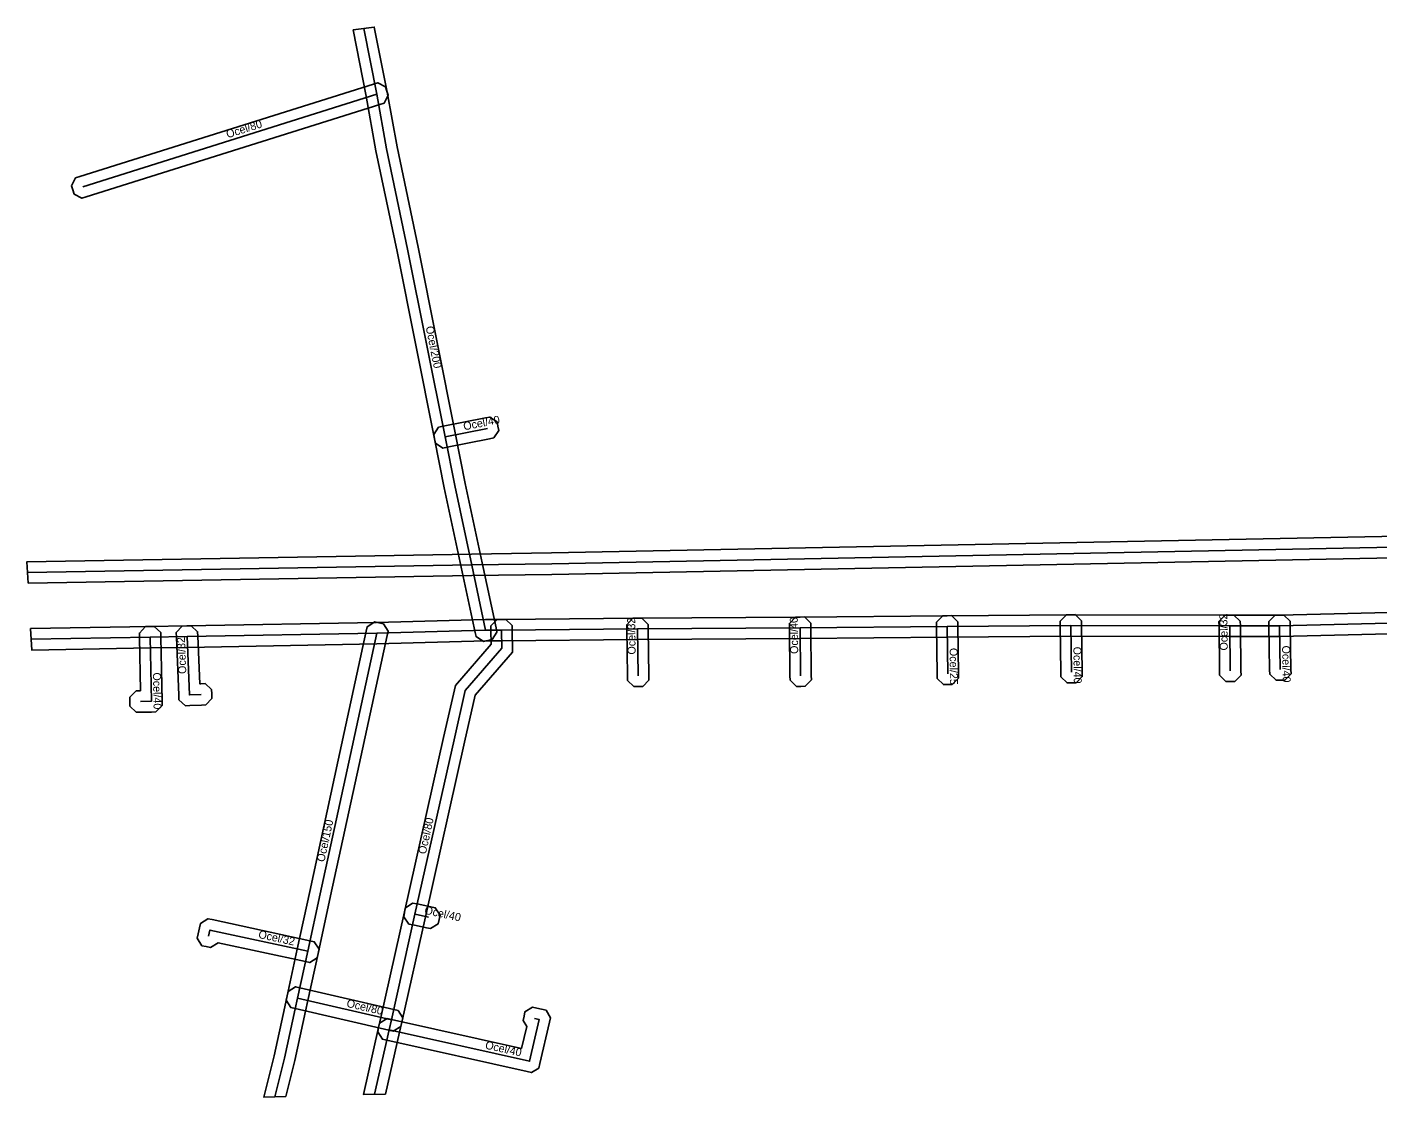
# Model space of a CAD drawing. Extents: x -702844 to -702342, y -1011731 to -1011542.
# Drawn here: x -702844.1 to -702717.5, y -1011730.8 to -1011630.5 of the extents above; entities that cross this region are included whole.
import ezdxf

# ---------------------------------------------------------------- set-up
doc = ezdxf.new("R2010")
doc.units = 0
for name, color, linetype in [('1', 7, 'Continuous'), ('14', 7, 'Continuous'), ('18', 7, 'Continuous'), ('20', 7, 'Continuous'), ('24', 7, 'Continuous')]:
    doc.layers.add(name, color=color, linetype=linetype)

msp = doc.modelspace()

# ---------------------------------------------------------------- linework, layer by layer
at = {"layer": '1'}
for points in [[(-702813.55, -1011630.76), (-702811.56, -1011630.49), (-702810.35, -1011636.6), (-702809.43, -1011641.71), (-702807.46, -1011651.12), (-702803.95, -1011668.69), (-702803.04, -1011673.26), (-702801.45, -1011680.7), (-702800.15, -1011686.8), (-702800.07, -1011687.21), (-702800.52, -1011687.9), (-702800.92, -1011687.99), (-702801.33, -1011688.08), (-702802.02, -1011687.62), (-702802.11, -1011687.22), (-702803.41, -1011681.12), (-702805, -1011673.67), (-702805.91, -1011669.08), (-702809.42, -1011651.52), (-702811.4, -1011642.09), (-702812.32, -1011636.97)], [(-702839.56, -1011644.62), (-702839.16, -1011644.5), (-702811.63, -1011635.84), (-702811.24, -1011635.71), (-702810.5, -1011636.09), (-702810.38, -1011636.49), (-702810.25, -1011636.88), (-702810.64, -1011637.62), (-702811.03, -1011637.74), (-702838.56, -1011646.41), (-702838.96, -1011646.53), (-702839.69, -1011646.15), (-702839.82, -1011645.76), (-702839.94, -1011645.36)], [(-702800.35, -1011669), (-702800.76, -1011669.08), (-702804.74, -1011669.87), (-702805.14, -1011669.95), (-702805.83, -1011669.48), (-702805.91, -1011669.08), (-702805.99, -1011668.67), (-702805.53, -1011667.98), (-702805.12, -1011667.9), (-702801.15, -1011667.12), (-702800.74, -1011667.04), (-702800.05, -1011667.5), (-702799.97, -1011667.91), (-702799.89, -1011668.31)], [(-702802.41, -1011681.9), (-702843.99, -1011682.6), (-702844.1, -1011680.6), (-702802.44, -1011679.9), (-702794.94, -1011679.78), (-702550.47, -1011674.95), (-702550.05, -1011674.94), (-702549.46, -1011675.51), (-702549.45, -1011675.93), (-702549.44, -1011676.34), (-702550.01, -1011676.94), (-702550.43, -1011676.95), (-702794.91, -1011681.78)], [(-702756.88, -1011686.23), (-702756.87, -1011686.65), (-702756.83, -1011691.09), (-702756.83, -1011691.51), (-702757.41, -1011692.1), (-702757.83, -1011692.1), (-702758.24, -1011692.11), (-702758.83, -1011691.53), (-702758.83, -1011691.11), (-702758.87, -1011686.67), (-702758.88, -1011686.25), (-702758.3, -1011685.66), (-702757.88, -1011685.66), (-702757.47, -1011685.65)], [(-702745.29, -1011686.13), (-702745.29, -1011686.55), (-702745.23, -1011690.95), (-702745.23, -1011691.36), (-702745.81, -1011691.95), (-702746.22, -1011691.96), (-702746.64, -1011691.96), (-702747.23, -1011691.38), (-702747.23, -1011690.97), (-702747.29, -1011686.57), (-702747.29, -1011686.16), (-702746.71, -1011685.56), (-702746.3, -1011685.56), (-702745.89, -1011685.55)], [(-702732.35, -1011691.24), (-702732.36, -1011690.83), (-702732.41, -1011686.62), (-702732.42, -1011686.2), (-702731.84, -1011685.61), (-702731.43, -1011685.6), (-702731.01, -1011685.6), (-702730.42, -1011686.18), (-702730.41, -1011686.59), (-702730.36, -1011690.81), (-702730.35, -1011691.22), (-702730.93, -1011691.81), (-702731.35, -1011691.82), (-702731.76, -1011691.82)], [(-702725.74, -1011686.18), (-702725.73, -1011686.59), (-702725.67, -1011690.69), (-702725.66, -1011691.11), (-702726.24, -1011691.7), (-702726.65, -1011691.71), (-702727.07, -1011691.71), (-702727.66, -1011691.14), (-702727.67, -1011690.72), (-702727.73, -1011686.62), (-702727.74, -1011686.21), (-702727.16, -1011685.61), (-702726.75, -1011685.61), (-702726.33, -1011685.6)], [(-702833.88, -1011692.7), (-702833.47, -1011692.69), (-702833.56, -1011687.7), (-702833.57, -1011687.28), (-702832.99, -1011686.68), (-702832.58, -1011686.68), (-702832.17, -1011686.67), (-702831.57, -1011687.24), (-702831.56, -1011687.66), (-702831.45, -1011693.66), (-702831.45, -1011694.07), (-702831.74, -1011694.37), (-702832.03, -1011694.67), (-702832.44, -1011694.68), (-702833.44, -1011694.69), (-702833.86, -1011694.7), (-702834.45, -1011694.12), (-702834.46, -1011693.7), (-702834.46, -1011693.29)], [(-702827.33, -1011694.02), (-702827.74, -1011694.03), (-702828.84, -1011694.08), (-702829.26, -1011694.09), (-702829.56, -1011693.81), (-702829.86, -1011693.53), (-702829.88, -1011693.11), (-702830.09, -1011687.66), (-702830.11, -1011687.24), (-702829.55, -1011686.63), (-702829.13, -1011686.62), (-702828.72, -1011686.6), (-702828.11, -1011687.16), (-702828.09, -1011687.58), (-702827.92, -1011692.04), (-702827.82, -1011692.03), (-702827.41, -1011692.02), (-702826.8, -1011692.58), (-702826.78, -1011692.99), (-702826.77, -1011693.41)], [(-702819.84, -1011730.71), (-702821.91, -1011730.76), (-702820.95, -1011726.9), (-702819.95, -1011722.3), (-702819.73, -1011721.28), (-702818.78, -1011716.89), (-702817.61, -1011711.5), (-702814.93, -1011699.18), (-702812.31, -1011687.09), (-702812.22, -1011686.69), (-702811.52, -1011686.24), (-702811.12, -1011686.33), (-702810.71, -1011686.42), (-702810.26, -1011687.11), (-702810.35, -1011687.52), (-702812.98, -1011699.6), (-702815.65, -1011711.92), (-702816.82, -1011717.31), (-702817.78, -1011721.71), (-702817.99, -1011722.72), (-702819, -1011727.35)], [(-702810.5, -1011730.48), (-702812.56, -1011730.53), (-702811.15, -1011724.25), (-702810.94, -1011723.3), (-702808.72, -1011713.42), (-702805.06, -1011697.07), (-702803.96, -1011692.19), (-702800.62, -1011688.33), (-702800.63, -1011687.01), (-702800.63, -1011686.59), (-702800.05, -1011686), (-702799.64, -1011686), (-702799.22, -1011686), (-702798.63, -1011686.58), (-702798.63, -1011686.99), (-702798.61, -1011689.07), (-702802.12, -1011693.11), (-702803.11, -1011697.51), (-702806.77, -1011713.86), (-702808.99, -1011723.74), (-702809.2, -1011724.69)], [(-702787.83, -1011691.72), (-702787.84, -1011691.3), (-702787.9, -1011686.91), (-702787.91, -1011686.5), (-702787.33, -1011685.9), (-702786.92, -1011685.9), (-702786.5, -1011685.89), (-702785.91, -1011686.47), (-702785.9, -1011686.88), (-702785.84, -1011691.28), (-702785.83, -1011691.69), (-702786.41, -1011692.28), (-702786.83, -1011692.29), (-702787.24, -1011692.3)], [(-702772.6, -1011691.71), (-702772.61, -1011691.29), (-702772.67, -1011686.79), (-702772.67, -1011686.38), (-702772.09, -1011685.78), (-702771.68, -1011685.78), (-702771.26, -1011685.77), (-702770.67, -1011686.35), (-702770.67, -1011686.77), (-702770.61, -1011691.27), (-702770.6, -1011691.68), (-702771.18, -1011692.27), (-702771.59, -1011692.28), (-702772.01, -1011692.28)], [(-702806.68, -1011714.89), (-702807.93, -1011714.62), (-702808.32, -1011714.56), (-702808.8, -1011713.88), (-702808.73, -1011713.47), (-702808.67, -1011713.07), (-702807.99, -1011712.59), (-702807.58, -1011712.65), (-702807.55, -1011712.66), (-702806.25, -1011712.94), (-702805.85, -1011713.03), (-702805.4, -1011713.72), (-702805.49, -1011714.13), (-702805.58, -1011714.54), (-702806.28, -1011714.98)], [(-702818.01, -1011718.07), (-702826.2, -1011716.3), (-702826.2, -1011716.32), (-702826.9, -1011716.76), (-702827.31, -1011716.67), (-702827.71, -1011716.58), (-702828.15, -1011715.88), (-702828.06, -1011715.48), (-702827.93, -1011714.89), (-702827.84, -1011714.49), (-702827.15, -1011714.05), (-702826.75, -1011714.13), (-702817.59, -1011716.12), (-702817.18, -1011716.21), (-702816.73, -1011716.9), (-702816.82, -1011717.31), (-702816.91, -1011717.71), (-702817.6, -1011718.16)], [(-702809.78, -1011724.59), (-702810.19, -1011724.49), (-702818.98, -1011722.47), (-702819.38, -1011722.38), (-702819.82, -1011721.67), (-702819.73, -1011721.27), (-702819.63, -1011720.87), (-702818.93, -1011720.43), (-702818.53, -1011720.52), (-702809.74, -1011722.55), (-702809.33, -1011722.64), (-702808.9, -1011723.34), (-702808.99, -1011723.74), (-702809.08, -1011724.15)], [(-702797.76, -1011726.21), (-702797.28, -1011724.14), (-702797.62, -1011723.58), (-702797.53, -1011723.18), (-702797.44, -1011722.77), (-702796.73, -1011722.34), (-702796.33, -1011722.43), (-702795.88, -1011722.54), (-702795.47, -1011722.63), (-702795.04, -1011723.34), (-702795.13, -1011723.74), (-702796.04, -1011727.63), (-702796.13, -1011728.04), (-702796.83, -1011728.47), (-702797.23, -1011728.38), (-702810.39, -1011725.44), (-702810.8, -1011725.35), (-702811.24, -1011724.65), (-702811.15, -1011724.25), (-702811.06, -1011723.84), (-702810.36, -1011723.4), (-702809.96, -1011723.49)]]:
    msp.add_lwpolyline(points, close=True, dxfattribs=at)
msp.add_lwpolyline([(-702713.92, -1011687.29), (-702726.72, -1011687.61), (-702731.28, -1011687.6), (-702731.37, -1011687.6), (-702746.29, -1011687.56), (-702757.86, -1011687.66), (-702771.66, -1011687.78), (-702786.9, -1011687.9), (-702799.62, -1011688), (-702801.11, -1011688.01), (-702811.31, -1011688.3), (-702829.08, -1011688.62), (-702832.54, -1011688.68), (-702843.65, -1011688.87), (-702843.76, -1011686.87), (-702832.58, -1011686.68), (-702829.11, -1011686.62), (-702811.35, -1011686.3), (-702801.15, -1011686.01), (-702799.64, -1011686), (-702786.91, -1011685.9), (-702771.67, -1011685.78), (-702757.88, -1011685.66), (-702746.29, -1011685.56), (-702731.45, -1011685.6), (-702731.36, -1011685.6), (-702726.74, -1011685.61), (-702713.96, -1011685.29)], dxfattribs=at)
at = {"layer": '14'}
for points in [[(-702801.13, -1011687.01), (-702802.43, -1011680.91), (-702804.02, -1011673.46), (-702804.93, -1011668.89), (-702808.44, -1011651.32), (-702810.42, -1011641.9), (-702811.33, -1011636.79), (-702812.55, -1011630.62)], [(-702838.86, -1011645.46), (-702811.33, -1011636.79)], [(-702800.95, -1011668.1), (-702804.93, -1011668.89)], [(-702843.7, -1011687.87), (-702832.56, -1011687.68), (-702829.09, -1011687.62), (-702811.33, -1011687.3), (-702801.13, -1011687.01), (-702799.63, -1011687), (-702786.9, -1011686.9), (-702771.67, -1011686.78), (-702757.87, -1011686.66), (-702746.29, -1011686.56), (-702731.41, -1011686.6), (-702731.32, -1011686.6), (-702726.73, -1011686.61), (-702713.94, -1011686.29), (-702695.28, -1011685.82), (-702680.63, -1011685.5), (-702663.12, -1011685.11), (-702631.83, -1011684.75), (-702621.57, -1011684.58), (-702605.18, -1011684.21), (-702593.89, -1011684.01), (-702582.58, -1011683.82)], [(-702786.84, -1011691.29), (-702786.9, -1011686.9)], [(-702771.61, -1011691.28), (-702771.67, -1011686.78)], [(-702757.87, -1011686.66), (-702757.83, -1011691.1)], [(-702746.29, -1011686.56), (-702746.23, -1011690.96)], [(-702731.36, -1011690.82), (-702731.41, -1011686.6)], [(-702726.73, -1011686.61), (-702726.67, -1011690.71)], [(-702832.56, -1011687.68), (-702832.45, -1011693.68), (-702833.46, -1011693.69)], [(-702827.78, -1011693.03), (-702828.88, -1011693.08), (-702829.09, -1011687.62)], [(-702820.87, -1011730.73), (-702819.98, -1011727.13), (-702818.97, -1011722.51), (-702818.75, -1011721.49), (-702817.8, -1011717.1), (-702816.63, -1011711.71), (-702813.95, -1011699.39), (-702811.33, -1011687.3)], [(-702799.63, -1011687), (-702799.61, -1011688.7), (-702803.04, -1011692.65), (-702804.08, -1011697.29), (-702807.75, -1011713.64), (-702809.96, -1011723.52), (-702810.17, -1011724.47), (-702811.53, -1011730.5)], [(-702806.47, -1011713.92), (-702807.73, -1011713.64), (-702807.75, -1011713.64)], [(-702817.8, -1011717.1), (-702826.96, -1011715.11), (-702827.09, -1011715.7)], [(-702796.56, -1011723.41), (-702796.1, -1011723.51), (-702797.01, -1011727.41), (-702810.17, -1011724.47)]]:
    msp.add_lwpolyline(points, dxfattribs=at)
at = {"layer": '18'}
msp.add_lwpolyline([(-702809.96, -1011723.52), (-702818.75, -1011721.49)], dxfattribs=at)
at = {"layer": '24'}
msp.add_lwpolyline([(-702550.45, -1011675.95), (-702794.92, -1011680.78), (-702802.43, -1011680.9), (-702844.04, -1011681.6)], dxfattribs=at)

# ---------------------------------------------------------------- texts
at = {"layer": '20'}
for s, rotation, p in [('Ocel/80', 17.4732, (-702825.3, -1011640.92)), ('Ocel/200', 281.293, (-702806.75, -1011658.59)), ('Ocel/40', 11.1658, (-702803.14, -1011668.29)), ('Ocel/32', 90.7342, (-702731.59, -1011688.91)), ('Ocel/32', 90.822, (-702787.07, -1011689.29)), ('Ocel/40', 90.7257, (-702771.84, -1011689.23)), ('Ocel/32', 92.234, (-702829.17, -1011691.1)), ('Ocel/25', 270.5027, (-702757.65, -1011688.68)), ('Ocel/40', 270.7162, (-702746.06, -1011688.56)), ('Ocel/40', 270.9222, (-702726.5, -1011688.46)), ('Ocel/40', 271.0123, (-702832.3, -1011690.98)), ('Ocel/80', 77.3647, (-702806.74, -1011708.05)), ('Ocel/150', 77.7453, (-702816.24, -1011708.78)), ('Ocel/40', 347.7202, (-702806.91, -1011713.58)), ('Ocel/32', 347.7609, (-702822.47, -1011715.84)), ('Ocel/80', 347.0206, (-702814.21, -1011722.3)), ('Ocel/40', 347.4067, (-702801.22, -1011726.22))]:
    msp.add_text(s, height=0.75, rotation=rotation, dxfattribs=at).set_placement(p)

doc.saveas('drawing.dxf')
